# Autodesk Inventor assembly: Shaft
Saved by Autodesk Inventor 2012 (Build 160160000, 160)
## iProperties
Created: 2011-12
Part Number: Shaft
Document SubType Name: Assembly
Designer: Admin
ClientObjectVersion: 1
Author: Admin
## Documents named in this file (2)
- C:\CMU\Datasets\Session 6\Cluster Ex 1\Workspaces\Workspace\GearBox-A\Design Accelerator\Shaft4.iam
- C:\CMU\Datasets\Session 6\Cluster Ex 1\Workspaces\Workspace\GearBox-A\Design Accelerator\Shaft4.ipt
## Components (1 placed, 1 different names)
1. Shaft:1
